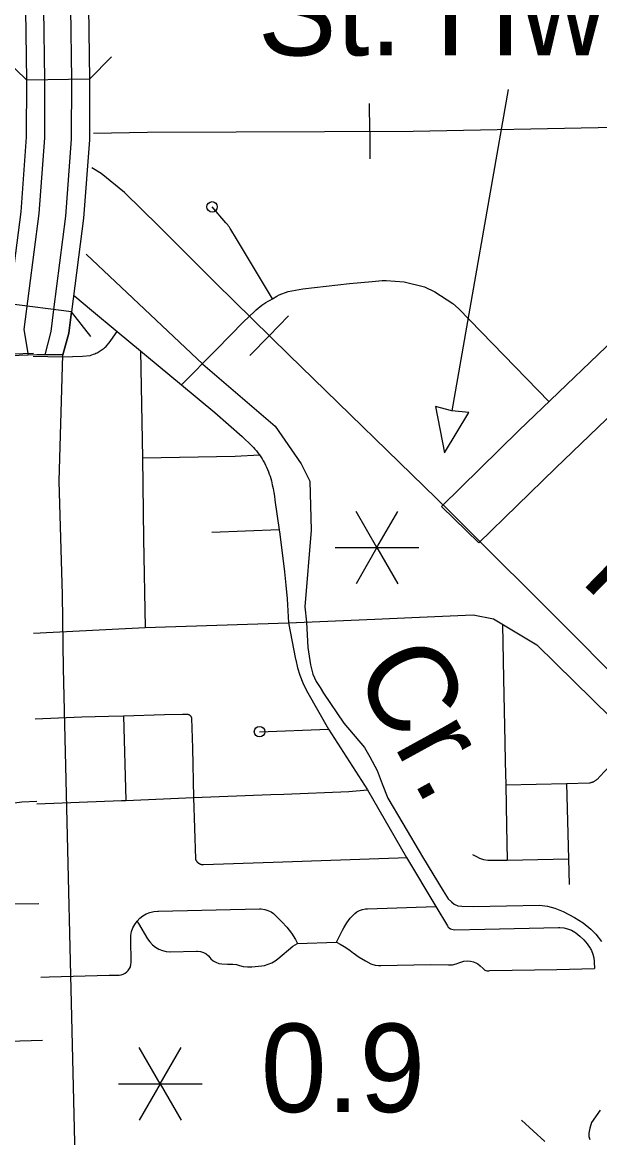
# Model space of a CAD drawing. Extents: x 309348 to 309445, y 336383 to 336484.
# Drawn here: x 309361.386 to 309362.64, y 336386.977 to 336389.399 of the extents above; entities that cross this region are included whole.
import ezdxf

# ---------------------------------------------------------------- set-up
doc = ezdxf.new("R2010")
doc.units = 0
doc.layers.add('R_Annotation', color=7, linetype='Continuous')

msp = doc.modelspace()

# ---------------------------------------------------------------- linework, layer by layer
at = {"layer": 'R_Annotation'}
for p, q in [((309361.5323, 336389.2753), (309361.3959, 336389.2735)), ((309361.4641, 336389.2744), (309361.4641, 336389.2744)), ((309362.4415, 336389.253), (309362.3193, 336388.5552)), ((309362.1407, 336389.1623), (309362.1404, 336389.2223)), ((309362.1407, 336389.1623), (309362.141, 336389.1023)), ((309361.4931, 336388.7705), (309361.3578, 336388.7879)), ((309361.4254, 336388.7792), (309361.4254, 336388.7792)), ((309361.9226, 336388.7184), (309361.9647, 336388.7612)), ((309361.9226, 336388.7184), (309361.8805, 336388.6756)), ((309362.1564, 336388.2582), (309362.111, 336388.337)), ((309362.1564, 336388.2582), (309362.2019, 336388.337)), ((309362.0655, 336388.2582), (309362.1564, 336388.2582)), ((309362.1564, 336388.2582), (309362.111, 336388.1795)), ((309362.1564, 336388.2582), (309362.2474, 336388.2582)), ((309362.1564, 336388.2582), (309362.2019, 336388.1795)), ((309361.6857, 336387.0941), (309361.6402, 336387.1728)), ((309361.6857, 336387.0941), (309361.7312, 336387.1728)), ((309361.5948, 336387.0941), (309361.6857, 336387.0941)), ((309361.6857, 336387.0941), (309361.6402, 336387.0153)), ((309361.6857, 336387.0941), (309361.7767, 336387.0941)), ((309361.6857, 336387.0941), (309361.7312, 336387.0153))]:
    msp.add_line(p, q, dxfattribs=at)
for points in [[(309361.5405, 336389.1581), (309361.658, 336389.16), (309362.2349, 336389.1628), (309362.6728, 336389.171), (309362.8132, 336389.171), (309362.9179, 336389.1821), (309363.0679, 336389.2082), (309363.1684, 336389.2399), (309363.2345, 336389.2619), (309363.3805, 336389.3322), (309363.6476, 336389.4823), (309363.85, 336389.5952), (309364.2851, 336389.8348), (309364.7009, 336390.0661), (309365.0795, 336390.2754), (309365.3356, 336390.4159), (309365.6068, 336390.5619), (309365.8547, 336390.7023), (309366.086, 336390.8332), (309366.2732, 336390.9351), (309366.4109, 336391.0136), (309366.6106, 336391.1237), (309366.7716, 336391.2242)], [(309361.5405, 336389.1581), (309361.658, 336389.16), (309362.2349, 336389.1628), (309362.6728, 336389.171), (309362.8132, 336389.171), (309362.9179, 336389.1821), (309363.0679, 336389.2082), (309363.1684, 336389.2399), (309363.2345, 336389.2619), (309363.3805, 336389.3322), (309363.6476, 336389.4823), (309363.85, 336389.5952), (309364.2851, 336389.8348), (309364.7009, 336390.0661), (309365.0795, 336390.2754), (309365.3356, 336390.4159), (309365.6068, 336390.5619), (309365.8547, 336390.7023), (309366.086, 336390.8332), (309366.2732, 336390.9351), (309366.4109, 336391.0136), (309366.6106, 336391.1237), (309366.7716, 336391.2242)], [(309361.3992, 336388.6762), (309361.3605, 336388.6746), (309361.351, 336388.735), (309361.3834, 336388.9874), (309361.3954, 336389.1492), (309361.3959, 336389.2735), (309361.3938, 336389.426), (309361.371, 336389.7884), (309361.3649, 336390.0172), (309361.3706, 336390.1172), (309361.3806, 336390.2178), (309361.3934, 336390.2819), (309361.5956, 336390.981), (309361.63, 336391.0922), (309361.6642, 336391.072)], [(309361.6642, 336391.072), (309361.6326, 336390.9699), (309361.431, 336390.2727), (309361.4189, 336390.212), (309361.4091, 336390.1141), (309361.4036, 336390.0167), (309361.4096, 336389.7901), (309361.4325, 336389.4275), (309361.4345, 336389.274), (309361.4341, 336389.1477), (309361.4219, 336388.9835), (309361.3896, 336388.7319), (309361.3992, 336388.6762)], [(309361.7209, 336391.0552), (309361.7596, 336391.0496), (309361.7263, 336390.9419), (309361.5261, 336390.2495), (309361.5157, 336390.1976), (309361.5066, 336390.1065), (309361.5014, 336390.0152), (309361.5073, 336389.7945), (309361.5302, 336389.4312), (309361.5323, 336389.2753), (309361.5318, 336389.1439), (309361.5192, 336388.9737), (309361.4931, 336388.7705), (309361.4871, 336388.7242), (309361.4743, 336388.6772), (309361.4357, 336388.677)], [(309361.4357, 336388.677), (309361.4486, 336388.7272), (309361.4547, 336388.7754), (309361.4807, 336388.9776), (309361.4932, 336389.1454), (309361.4936, 336389.2748), (309361.4916, 336389.4297), (309361.4687, 336389.7927), (309361.4627, 336390.0158), (309361.4681, 336390.1095), (309361.4774, 336390.2033), (309361.4885, 336390.2587), (309361.6893, 336390.953), (309361.7209, 336391.0552)], [(309361.347, 336389.3211), (309361.3959, 336389.2735)], [(309361.5323, 336389.2753), (309361.5799, 336389.3242)], [(309362.911, 336387.7375), (309362.5888, 336388.0639), (309362.312, 336388.3393), (309361.9651, 336388.6767), (309361.8067, 336388.8323), (309361.6828, 336388.9562), (309361.6085, 336389.0292), (309361.5575, 336389.0705), (309361.5372, 336389.083)], [(309365.7726, 336384.9236), (309365.7018, 336384.9944), (309365.5394, 336385.1596), (309365.3797, 336385.3125), (309365.1979, 336385.4888), (309365.0657, 336385.6182), (309364.7862, 336385.895), (309364.577, 336386.0988), (309364.4338, 336386.242), (309364.2424, 336386.4334), (309364.146, 336386.5243), (309363.5374, 336387.1261), (309363.3584, 336387.301), (309363.1271, 336387.531), (309362.911, 336387.7375), (309362.5888, 336388.0639), (309362.312, 336388.3393), (309361.9651, 336388.6767), (309361.8067, 336388.8323), (309361.6828, 336388.9562), (309361.6085, 336389.0292), (309361.5575, 336389.0705), (309361.5372, 336389.083)], [(309361.9293, 336388.7982), (309361.8511, 336388.9288), (309361.8394, 336388.9487), (309361.8378, 336388.9514), (309361.8361, 336388.954), (309361.8344, 336388.9565), (309361.8325, 336388.959), (309361.8306, 336388.9614), (309361.8285, 336388.9637), (309361.7984, 336388.9981)], [(309362.3781, 336388.2685), (309362.2968, 336388.3479), (309362.465, 336388.5125), (309362.7234, 336388.7604), (309362.8876, 336388.9226)], [(309361.5247, 336388.8951), (309361.7786, 336388.6568), (309361.9354, 336388.522), (309361.9918, 336388.4405), (309362.0106, 336388.4029), (309362.0137, 336388.2963), (309362, 336388.1296)], [(309362.9675, 336388.8417), (309362.8027, 336388.6789), (309362.5441, 336388.4308), (309362.3781, 336388.2685)], [(309361.9293, 336388.7982), (309361.9387, 336388.8044), (309361.9444, 336388.8075), (309361.964, 336388.8143), (309361.9958, 336388.82), (309362.0972, 336388.8318), (309362.146, 336388.8362), (309362.1678, 336388.838), (309362.1767, 336388.8383), (309362.2158, 336388.8357), (309362.2599, 336388.8248), (309362.2825, 336388.8139), (309362.3214, 336388.788), (309362.3336, 336388.7778), (309362.5303, 336388.5751)], [(309361.4997, 336388.8048), (309361.5002, 336388.8043), (309361.5362, 336388.7736), (309361.5921, 336388.7274)], [(309361.8077, 336388.6885), (309361.8669, 336388.7484), (309361.8903, 336388.7708), (309361.8942, 336388.7744), (309361.8983, 336388.7779), (309361.9024, 336388.7812), (309361.9066, 336388.7844), (309361.911, 336388.7875), (309361.9154, 336388.7904), (309361.92, 336388.7932), (309361.9246, 336388.7958), (309361.9293, 336388.7982)], [(309361.4743, 336388.6772), (309361.4871, 336388.7242), (309361.4931, 336388.7705)], [(309361.5348, 336388.7165), (309361.4931, 336388.7705)], [(309361.4099, 336388.6741), (309361.4733, 336388.6724), (309361.5169, 336388.6743), (309361.5334, 336388.6757), (309361.537, 336388.6767), (309361.5411, 336388.6784), (309361.5436, 336388.6794), (309361.546, 336388.6804), (309361.5485, 336388.6815), (309361.5508, 336388.6827), (309361.5532, 336388.684), (309361.5555, 336388.6854), (309361.5577, 336388.6868), (309361.5599, 336388.6883), (309361.562, 336388.6899), (309361.5641, 336388.6915), (309361.5662, 336388.6933), (309361.5681, 336388.695), (309361.57, 336388.6969), (309361.5747, 336388.7026), (309361.5788, 336388.7077), (309361.5921, 336388.7274)], [(309361.5921, 336388.7274), (309361.6432, 336388.6852)], [(309361.4105, 336388.6799), (309361.3172, 336388.6769), (309361.1765, 336388.6728), (309361.023, 336388.6655), (309360.9387, 336388.6619), (309360.8767, 336388.6583), (309360.7266, 336388.6504), (309360.6818, 336388.649), (309360.6207, 336388.648), (309360.46, 336388.6433), (309360.187, 336388.633)], [(309361.4743, 336388.6772), (309361.4175, 336388.677), (309361.3605, 336388.6746), (309361.3523, 336388.403), (309361.3596, 336388.1531), (309361.3623, 336387.9937)], [(309361.4759, 336387.9956), (309361.4732, 336388.1557), (309361.466, 336388.4029), (309361.4743, 336388.6772)], [(309361.6432, 336388.6852), (309361.6471, 336388.4532)], [(309361.6432, 336388.6852), (309361.6558, 336388.6747), (309361.7317, 336388.6118)], [(309361.7317, 336388.6118), (309361.8077, 336388.6885)], [(309361.7317, 336388.6118), (309361.8043, 336388.5515), (309361.8341, 336388.5256), (309361.8637, 336388.4996), (309361.8845, 336388.4794), (309361.8881, 336388.4758), (309361.8915, 336388.472), (309361.8948, 336388.4681), (309361.898, 336388.4641), (309361.9011, 336388.46)], [(309361.6471, 336388.4532), (309361.8486, 336388.457), (309361.9011, 336388.46)], [(309361.9011, 336388.46), (309361.9041, 336388.4557), (309361.907, 336388.4513), (309361.9097, 336388.4468), (309361.9122, 336388.4422), (309361.9146, 336388.4375), (309361.9169, 336388.4328), (309361.919, 336388.428), (309361.9209, 336388.4231), (309361.9227, 336388.4181), (309361.9243, 336388.4131), (309361.9258, 336388.4081), (309361.9271, 336388.403), (309361.9292, 336388.3948), (309361.9311, 336388.3866), (309361.9326, 336388.3783), (309361.934, 336388.37), (309361.935, 336388.3616), (309361.9443, 336388.2966)], [(309361.6471, 336388.4532), (309361.6498, 336388.2773)], [(309361.9443, 336388.2966), (309361.7981, 336388.2912)], [(309361.9443, 336388.2966), (309361.9456, 336388.2876), (309361.9556, 336388.2056), (309361.9588, 336388.1764), (309361.9613, 336388.147), (309361.9646, 336388.0948)], [(309361.6498, 336388.2773), (309361.6529, 336388.0849)], [(309362, 336388.1296), (309362.0032, 336388.0963), (309362.0065, 336388.0414), (309362.012, 336388.0035), (309362.0171, 336387.9836), (309362.0245, 336387.9679), (309362.0328, 336387.9546), (309362.0402, 336387.9421), (309362.0849, 336387.8774), (309362.1297, 336387.8243), (309362.1412, 336387.804), (309362.1569, 336387.7745), (309362.1675, 336387.7454), (309362.18, 336387.714), (309362.2128, 336387.659), (309362.2557, 336387.587), (309362.3, 336387.5131), (309362.3115, 336387.496), (309362.3184, 336387.4891), (309362.3244, 336387.484), (309362.3318, 336387.4808), (309362.3406, 336387.4799), (309362.3664, 336387.4794), (309362.5095, 336387.4817), (309362.527, 336387.4799), (309362.5427, 336387.4757), (309362.5612, 336387.4683), (309362.5856, 336387.4549), (309362.6046, 336387.4434), (309362.6207, 336387.43), (309362.6322, 336387.4189), (309362.6442, 336387.4028)], [(309361.6529, 336388.0849), (309361.9646, 336388.0948)], [(309361.9646, 336388.0948), (309362.1522, 336388.1027)], [(309361.9646, 336388.0948), (309361.9796, 336388.0163), (309361.98, 336388.0145), (309361.9839, 336387.9976), (309361.9891, 336387.9811), (309361.9954, 336387.965), (309362.0028, 336387.9494), (309362.0061, 336387.9432), (309362.0516, 336387.8641)], [(309362.1522, 336388.1027), (309362.2325, 336388.1063)], [(309362.2325, 336388.1063), (309362.3652, 336388.1122)], [(309362.3652, 336388.1122), (309362.4093, 336388.1034), (309362.5035, 336388.0474), (309362.6654, 336387.8885), (309363.154, 336387.3939), (309363.5307, 336387.0083)], [(309362.4292, 336388.0916), (309362.4312, 336387.9736), (309362.4342, 336387.8357), (309362.435, 336387.7929), (309362.4361, 336387.7429)], [(309361.4103, 336388.0728), (309361.6529, 336388.0849)], [(309361.5008, 336386.9359), (309361.4759, 336387.9956)], [(309361.6063, 336387.8932), (309361.6949, 336387.8962), (309361.7345, 336387.8965), (309361.7441, 336387.8966), (309361.7444, 336387.8966), (309361.7447, 336387.8966), (309361.7451, 336387.8966), (309361.7454, 336387.8965), (309361.7457, 336387.8965), (309361.746, 336387.8964), (309361.7464, 336387.8964), (309361.7467, 336387.8963), (309361.747, 336387.8962), (309361.7473, 336387.8961), (309361.7476, 336387.896), (309361.7479, 336387.8958), (309361.7482, 336387.8957), (309361.7485, 336387.8956), (309361.7488, 336387.8954), (309361.7491, 336387.8952), (309361.7494, 336387.8951), (309361.7497, 336387.8949), (309361.7499, 336387.8947), (309361.7502, 336387.8945), (309361.7504, 336387.8943)], [(309361.4141, 336387.8867), (309361.5152, 336387.8907), (309361.5731, 336387.8921), (309361.6063, 336387.8932)], [(309361.6063, 336387.8932), (309361.6109, 336387.7093)], [(309361.7504, 336387.8943), (309361.7507, 336387.894), (309361.7509, 336387.8938), (309361.7511, 336387.8936), (309361.7514, 336387.8933), (309361.7516, 336387.8931), (309361.7518, 336387.8928), (309361.752, 336387.8925), (309361.7521, 336387.8922), (309361.7523, 336387.892), (309361.7525, 336387.8917), (309361.7526, 336387.8914), (309361.7528, 336387.8911), (309361.7529, 336387.8908), (309361.753, 336387.8905), (309361.7531, 336387.8902), (309361.7532, 336387.8899), (309361.7533, 336387.8895), (309361.7534, 336387.8892), (309361.7535, 336387.8889), (309361.7535, 336387.8886), (309361.7536, 336387.8882), (309361.7561, 336387.8227), (309361.7583, 336387.7157)], [(309361.9014, 336387.8586), (309362.0516, 336387.8641)], [(309362.0516, 336387.8641), (309362.1363, 336387.7321)], [(309362.5685, 336387.7459), (309362.6184, 336387.7475), (309362.6196, 336387.7477), (309362.6209, 336387.748), (309362.622, 336387.7484), (309362.6232, 336387.7487), (309362.6244, 336387.7491), (309362.6255, 336387.7496), (309362.6267, 336387.7501), (309362.6278, 336387.7506), (309362.6289, 336387.7512), (309362.63, 336387.7518), (309362.631, 336387.7525), (309362.6321, 336387.7531), (309362.6331, 336387.7538), (309362.6341, 336387.7546), (309362.635, 336387.7554), (309362.636, 336387.7562), (309362.6369, 336387.7571), (309362.6377, 336387.7579), (309362.6386, 336387.7588), (309362.7142, 336387.8391)], [(309361.9545, 336387.7231), (309362.0951, 336387.7288), (309362.1363, 336387.7321)], [(309362.1363, 336387.7321), (309362.2209, 336387.5854)], [(309362.4361, 336387.7429), (309362.5685, 336387.7459)], [(309362.4361, 336387.7429), (309362.4382, 336387.654), (309362.4391, 336387.5794)], [(309362.5685, 336387.7459), (309362.5722, 336387.5827)], [(309360.8021, 336387.6663), (309360.9771, 336387.674), (309361.1513, 336387.6778), (309361.3147, 336387.684), (309361.3347, 336387.6886), (309361.3692, 336387.7039), (309361.3853, 336387.7062), (309361.4178, 336387.7078)], [(309361.4179, 336387.7023), (309361.6016, 336387.7089), (309361.6109, 336387.7093)], [(309361.6109, 336387.7093), (309361.7583, 336387.7157)], [(309361.7583, 336387.7157), (309361.9261, 336387.7219), (309361.9545, 336387.7231)], [(309361.7583, 336387.7157), (309361.7621, 336387.5823), (309361.7623, 336387.5818), (309361.7626, 336387.5812), (309361.7628, 336387.5806), (309361.7631, 336387.5801), (309361.7633, 336387.5795), (309361.7636, 336387.579), (309361.7639, 336387.5784), (309361.7643, 336387.5779), (309361.7646, 336387.5774), (309361.765, 336387.5769), (309361.7654, 336387.5764), (309361.7658, 336387.576), (309361.7662, 336387.5755), (309361.7666, 336387.5751), (309361.7671, 336387.5746), (309361.7675, 336387.5742), (309361.768, 336387.5738), (309361.7685, 336387.5735), (309361.769, 336387.5731)], [(309361.769, 336387.5731), (309361.7695, 336387.5728), (309361.77, 336387.5724), (309361.7705, 336387.5721), (309361.7711, 336387.5718), (309361.7716, 336387.5716), (309361.7722, 336387.5713), (309361.7728, 336387.5711), (309361.7733, 336387.5709), (309361.7739, 336387.5707), (309361.7745, 336387.5705), (309361.7751, 336387.5703), (309361.7757, 336387.5702), (309361.7763, 336387.5701), (309361.7769, 336387.57), (309361.7775, 336387.5699), (309361.7781, 336387.5699), (309361.7787, 336387.5699), (309361.7794, 336387.5698), (309361.78, 336387.5699), (309361.9309, 336387.5756), (309362.2027, 336387.5848), (309362.2209, 336387.5854)], [(309362.2209, 336387.5854), (309362.2842, 336387.4793)], [(309362.3643, 336387.5919), (309362.3653, 336387.5913), (309362.3753, 336387.586), (309362.376, 336387.5856), (309362.3794, 336387.5842), (309362.3882, 336387.5814), (309362.3972, 336387.5798), (309362.4051, 336387.5794), (309362.4391, 336387.5794)], [(309362.4391, 336387.5794), (309362.5722, 336387.5827)], [(309362.5722, 336387.5827), (309362.5736, 336387.5265)], [(309361.0169, 336387.4731), (309361.1226, 336387.4766), (309361.3562, 336387.4851), (309361.4222, 336387.4857)], [(309361.6355, 336387.4472), (309361.6414, 336387.4534), (309361.6481, 336387.4587), (309361.6555, 336387.4629), (309361.6635, 336387.4661), (309361.6718, 336387.4681), (309361.6803, 336387.4689), (309361.6817, 336387.4689), (309361.9014, 336387.4741), (309361.9053, 336387.474), (309361.9127, 336387.4729), (309361.9198, 336387.4707), (309361.9265, 336387.4672), (309361.9315, 336387.4636), (309361.9385, 336387.4575), (309361.9501, 336387.4461), (309361.9609, 336387.4339), (309361.9707, 336387.4209), (309361.9795, 336387.4073), (309361.9842, 336387.399)], [(309362.0685, 336387.4014), (309362.0814, 336387.4274), (309362.0844, 336387.4331), (309362.091, 336387.4436), (309362.0985, 336387.4534), (309362.1069, 336387.4624), (309362.1083, 336387.4637), (309362.1127, 336387.4673), (309362.1186, 336387.4706), (309362.1249, 336387.4728), (309362.1315, 336387.4739), (309362.1357, 336387.4739), (309362.2842, 336387.4793)], [(309362.2842, 336387.4793), (309362.3094, 336387.4371), (309362.3095, 336387.437), (309362.3113, 336387.4345), (309362.3135, 336387.4324), (309362.316, 336387.4307), (309362.3188, 336387.4295), (309362.3217, 336387.4288), (309362.3248, 336387.4286), (309362.3249, 336387.4286), (309362.3909, 336387.4295), (309362.5511, 336387.4332), (309362.5534, 336387.4332), (309362.5621, 336387.4324), (309362.5706, 336387.4305), (309362.5788, 336387.4274), (309362.5864, 336387.4232), (309362.5881, 336387.422), (309362.5883, 336387.4219), (309362.5974, 336387.4148), (309362.6057, 336387.4068), (309362.6132, 336387.398), (309362.6197, 336387.3884), (309362.6203, 336387.3873), (309362.6223, 336387.3836), (309362.6254, 336387.3759), (309362.6274, 336387.3678), (309362.6282, 336387.3596), (309362.6282, 336387.3583), (309362.6289, 336387.3444)], [(309361.5749, 336387.3299), (309361.5964, 336387.3303), (309361.6009, 336387.3308), (309361.6054, 336387.3321), (309361.6095, 336387.3342), (309361.6132, 336387.3369), (309361.6164, 336387.3402), (309361.619, 336387.3441), (309361.6209, 336387.3483), (309361.622, 336387.3528), (309361.6223, 336387.3574), (309361.6223, 336387.3578), (309361.6216, 336387.4081), (309361.6221, 336387.4162), (309361.6237, 336387.4246), (309361.6265, 336387.4327), (309361.6305, 336387.4403), (309361.6355, 336387.4472)], [(309361.6355, 336387.4472), (309361.6386, 336387.4422), (309361.6583, 336387.4089), (309361.663, 336387.4021), (309361.6688, 336387.3959), (309361.6754, 336387.3907), (309361.6826, 336387.3864), (309361.6904, 336387.3833), (309361.6986, 336387.3813), (309361.707, 336387.3806), (309361.7077, 336387.3806), (309361.7648, 336387.3822), (309361.7667, 336387.3822), (309361.7733, 336387.3814), (309361.7796, 336387.3793), (309361.7854, 336387.3761), (309361.7905, 336387.3719), (309361.7934, 336387.3686), (309361.7959, 336387.3657), (309361.8009, 336387.3613), (309361.8067, 336387.3579), (309361.813, 336387.3556), (309361.8196, 336387.3545), (309361.8198, 336387.3545), (309361.8322, 336387.354), (309361.8398, 336387.354), (309361.8436, 336387.3539), (309361.8515, 336387.3529), (309361.8576, 336387.3512), (309361.8576, 336387.3512), (309361.8662, 336387.349), (309361.875, 336387.348), (309361.8838, 336387.3481), (309361.8847, 336387.3482), (309361.9063, 336387.3504), (309361.912, 336387.3513), (309361.9202, 336387.3535), (309361.9281, 336387.3569), (309361.9354, 336387.3613), (309361.941, 336387.3658), (309361.9737, 336387.3927), (309361.9785, 336387.3961), (309361.9842, 336387.399)], [(309361.9842, 336387.399), (309362.0685, 336387.4014)], [(309362.0685, 336387.4014), (309362.0763, 336387.3974), (309362.0856, 336387.3921), (309362.0976, 336387.3841), (309362.1027, 336387.3802), (309362.105, 336387.3785), (309362.1181, 336387.3692), (309362.1319, 336387.3609), (309362.1435, 336387.3549), (309362.1455, 336387.3541), (309362.1524, 336387.3518), (309362.1596, 336387.3508), (309362.1647, 336387.3508), (309362.2724, 336387.353), (309362.3119, 336387.3522), (309362.312, 336387.3522), (309362.3205, 336387.3527), (309362.3287, 336387.3544), (309362.3366, 336387.3573), (309362.3367, 336387.3573), (309362.3388, 336387.3582), (309362.3455, 336387.3602), (309362.3525, 336387.3609), (309362.3596, 336387.3604), (309362.3664, 336387.3588), (309362.3728, 336387.3559), (309362.3755, 336387.3543), (309362.381, 336387.3502), (309362.3872, 336387.3443), (309362.3876, 336387.3438), (309362.3892, 336387.3423), (309362.391, 336387.341), (309362.3931, 336387.3401), (309362.3952, 336387.3396), (309362.3974, 336387.3395), (309362.3997, 336387.3397), (309362.4015, 336387.3402), (309362.547, 336387.3424)], [(309362.547, 336387.3424), (309362.6289, 336387.3444)], [(309361.4261, 336387.3256), (309361.4446, 336387.3261), (309361.5749, 336387.3299)], [(309361.1334, 336387.1801), (309361.1359, 336387.1802), (309361.3072, 336387.1854), (309361.4298, 336387.1887)], [(309362.6415, 336387.0366), (309362.6225, 336387.0098), (309362.6189, 336386.9978), (309362.617, 336386.9867), (309362.617, 336386.9794), (309362.6185, 336386.9731)], [(309362.5208, 336386.9685), (309362.4707, 336387.0148)]]:
    msp.add_lwpolyline(points, dxfattribs=at)
msp.add_lwpolyline([(309362.3563, 336388.552), (309362.3193, 336388.5552), (309362.2835, 336388.5648), (309362.3033, 336388.4638)], close=True, dxfattribs=at)
for centre in [(309361.7984, 336388.9981), (309361.9014, 336387.8586)]:
    msp.add_circle(centre, 0.0114, dxfattribs=at)

# ---------------------------------------------------------------- texts
for s, p in [('St. Hwy.', (309361.8976, 336389.3269)), ('0.9', (309361.9042, 336387.0327))]:
    msp.add_text(s, height=0.19206, dxfattribs=at).set_placement(p)
for s, rotation, p in [('RAILROAD', 315.7198, (309362.5944, 336388.1869)), ('Cr.', 298.7458, (309362.1026, 336387.9919))]:
    msp.add_text(s, height=0.19206, rotation=rotation, dxfattribs=at).set_placement(p)

doc.saveas('drawing.dxf')
